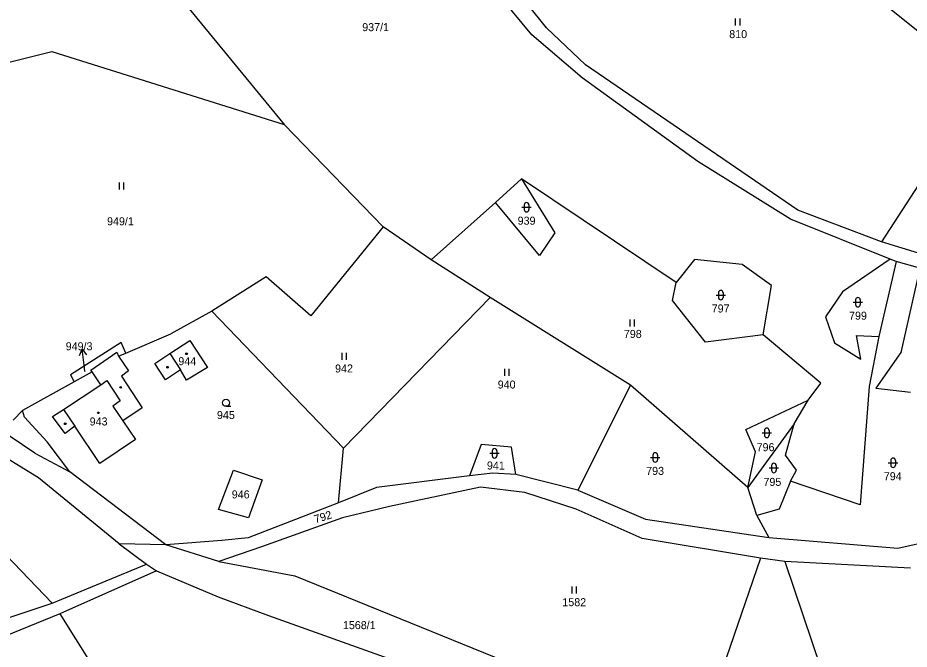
# Model space of a CAD drawing. Extents: x -670359 to -668019, y -978807 to -976674.
# Drawn here: x -669348.5 to -669159.3, y -977924.2 to -977790.2 of the extents above; entities that cross this region are included whole.
import ezdxf

# ---------------------------------------------------------------- set-up
doc = ezdxf.new("R2010")
doc.units = 0
for name, color, linetype in [('Hranice parcel', 7, 'Continuous'), ('Parcelní čísla', 7, 'Continuous'), ('Vnitřní kresba', 7, 'Continuous'), ('Značky budov', 7, 'Continuous'), ('Značky kultur', 7, 'Continuous')]:
    doc.layers.add(name, color=color, linetype=linetype)

msp = doc.modelspace()

# ---------------------------------------------------------------- linework, layer by layer
at = {"layer": 'Hranice parcel'}
for p, q in [((-669325.57, -977861.32), (-669316, -977857.26)), ((-669326.53, -977859.06), (-669337.33, -977865.97)), ((-669325.57, -977861.32), (-669326.53, -977859.06)), ((-669332.99, -977864.96), (-669327.49, -977861.17)), ((-669327.49, -977861.17), (-669327.09, -977861.96)), ((-669327.09, -977861.96), (-669325.57, -977861.32)), ((-669332.73, -977865.34), (-669336.54, -977867.45)), ((-669332.73, -977865.34), (-669332.99, -977864.96)), ((-669337.33, -977865.97), (-669336.54, -977867.45)), ((-669336.54, -977867.45), (-669347.5, -977873.51))]:
    msp.add_line(p, q, dxfattribs=at)
for points in [[(-669239.37, -977793.76), (-669277.73, -977747.47)], [(-669155.29, -977794.72), (-669193.7, -977763.96)], [(-669236.24, -977792.33), (-669255.54, -977768.2)], [(-669315.98, -977783.46), (-669291.93, -977812.85)], [(-669227.94, -977800.19), (-669236.24, -977792.33)], [(-669228.67, -977802.91), (-669239.37, -977793.76)], [(-669182.88, -977830.97), (-669227.94, -977800.19)], [(-669142.34, -977802.6), (-669165.12, -977837.74)], [(-669204.14, -977820.67), (-669228.67, -977802.91)], [(-669291.93, -977812.85), (-669270.94, -977834.54)], [(-669184.48, -977832.88), (-669204.14, -977820.67)], [(-669241.56, -977824.37), (-669247.06, -977829.36)], [(-669241.56, -977824.37), (-669234.47, -977835.84)], [(-669208.71, -977846.34), (-669241.56, -977824.37)], [(-669247.06, -977829.36), (-669260.75, -977841.51)], [(-669237.72, -977840.65), (-669247.06, -977829.36)], [(-669165.12, -977837.74), (-669182.88, -977830.97)], [(-669163.29, -977841.43), (-669184.48, -977832.88)], [(-669270.94, -977834.54), (-669286.27, -977853.41)], [(-669260.75, -977841.51), (-669270.94, -977834.54)], [(-669234.47, -977835.84), (-669237.72, -977840.65)], [(-669151.04, -977842.02), (-669165.12, -977837.74)], [(-669248.23, -977849.51), (-669260.75, -977841.51)], [(-669204.85, -977841.47), (-669208.71, -977846.34)], [(-669194.69, -977842.54), (-669204.85, -977841.47)], [(-669188.45, -977846.96), (-669194.69, -977842.54)], [(-669163.29, -977841.43), (-669173.4, -977848.36)], [(-669162.01, -977841.91), (-669165.67, -977857.83)], [(-669162.01, -977841.91), (-669163.29, -977841.43)], [(-669156.97, -977843.29), (-669162.01, -977841.91)], [(-669156.97, -977843.29), (-669161.03, -977861.2)], [(-669295.75, -977845.15), (-669307.31, -977852.42)], [(-669286.27, -977853.41), (-669295.75, -977845.15)], [(-669209.53, -977850.18), (-669208.71, -977846.34)], [(-669190.25, -977857.44), (-669188.45, -977846.96)], [(-669279.32, -977881.5), (-669248.23, -977849.51)], [(-669218.39, -977868.16), (-669248.23, -977849.51)], [(-669202.51, -977859), (-669209.53, -977850.18)], [(-669173.4, -977848.36), (-669177.03, -977853.63)], [(-669307.31, -977852.42), (-669316, -977857.26)], [(-669279.32, -977881.5), (-669307.31, -977852.42)], [(-669177.03, -977853.63), (-669175.12, -977859.16)], [(-669190.25, -977857.44), (-669202.51, -977859)], [(-669178.03, -977867.71), (-669190.25, -977857.44)], [(-669169.53, -977862.62), (-669170.47, -977857.57)], [(-669170.47, -977857.57), (-669165.67, -977857.83)], [(-669316.22, -977861.42), (-669311.99, -977858.68)], [(-669311.99, -977858.68), (-669308.2, -977864.41)], [(-669175.12, -977859.16), (-669169.53, -977862.62)], [(-669165.67, -977857.83), (-669167.78, -977868.46)], [(-669319.4, -977863.52), (-669316.22, -977861.42)], [(-669161.03, -977861.2), (-669166.34, -977868.79)], [(-669327.09, -977861.96), (-669324.99, -977865.07)], [(-669330.9, -977868.06), (-669332.73, -977865.34)], [(-669324.99, -977865.07), (-669326.51, -977866.27)], [(-669317.15, -977867.02), (-669319.4, -977863.52)], [(-669313.96, -977864.92), (-669317.15, -977867.02)], [(-669312.67, -977867.07), (-669313.96, -977864.92)], [(-669308.2, -977864.41), (-669312.67, -977867.07)], [(-669326.51, -977866.27), (-669322.07, -977872.96)], [(-669338.79, -977873.3), (-669330.9, -977868.06)], [(-669218.39, -977868.16), (-669229.6, -977890.45)], [(-669193.48, -977889.84), (-669218.39, -977868.16)], [(-669180.69, -977871.31), (-669178.03, -977867.71)], [(-669167.78, -977868.46), (-669169.63, -977893.58)], [(-669166.34, -977868.79), (-669158.98, -977869.61)], [(-669193.92, -977877.59), (-669180.69, -977871.31)], [(-669183.67, -977876.34), (-669180.69, -977871.31)], [(-669344.14, -977887.8), (-669365.81, -977874.5)], [(-669349.49, -977875.6), (-669347.5, -977873.51)], [(-669347.09, -977874.95), (-669347.5, -977873.51)], [(-669341.1, -977874.83), (-669338.79, -977873.3)], [(-669322.07, -977872.96), (-669326.22, -977875.7)], [(-669344.89, -977882.61), (-669355.46, -977875.53)], [(-669342.27, -977880.19), (-669347.09, -977874.95)], [(-669338.44, -977878.41), (-669341.1, -977874.83)], [(-669326.22, -977875.7), (-669323.48, -977879.68)], [(-669183.67, -977876.34), (-669193.48, -977889.84)], [(-669185.53, -977882.98), (-669183.67, -977876.34)], [(-669336.37, -977876.88), (-669338.44, -977878.41)], [(-669331.05, -977884.76), (-669336.37, -977876.88)], [(-669191.86, -977882.32), (-669193.92, -977877.59)], [(-669337.43, -977886.56), (-669342.27, -977880.19)], [(-669323.48, -977879.68), (-669331.05, -977884.76)], [(-669280.38, -977893.09), (-669279.32, -977881.5)], [(-669250.14, -977880.76), (-669252.58, -977887.41)], [(-669243.66, -977881.28), (-669250.14, -977880.76)], [(-669242.75, -977887.11), (-669243.66, -977881.28)], [(-669193.48, -977889.84), (-669191.86, -977882.32)], [(-669344.89, -977882.61), (-669337.43, -977886.56)], [(-669183.14, -977886.18), (-669185.53, -977882.98)], [(-669326.98, -977901.79), (-669344.14, -977887.8)], [(-669317.06, -977902.06), (-669337.43, -977886.56)], [(-669305.88, -977894.52), (-669302.73, -977886.19)], [(-669302.73, -977886.19), (-669296.64, -977888.23)], [(-669252.58, -977887.41), (-669272.35, -977889.85)], [(-669247.63, -977886.82), (-669252.58, -977887.41)], [(-669242.75, -977887.11), (-669247.63, -977886.82)], [(-669229.6, -977890.45), (-669242.75, -977887.11)], [(-669184.43, -977888.5), (-669183.14, -977886.18)], [(-669296.64, -977888.23), (-669299.55, -977896.32)], [(-669272.35, -977889.85), (-669280.38, -977893.09)], [(-669250.25, -977889.82), (-669269.58, -977893.93)], [(-669240.82, -977890.96), (-669250.25, -977889.82)], [(-669191.58, -977895.84), (-669193.48, -977889.84)], [(-669184.43, -977888.5), (-669186.85, -977894.5)], [(-669169.63, -977893.58), (-669184.43, -977888.5)], [(-669229.97, -977894.44), (-669240.82, -977890.96)], [(-669229.6, -977890.45), (-669215.21, -977896.58)], [(-669280.38, -977893.09), (-669299.61, -977900.56)], [(-669360.92, -977893.91), (-669341.2, -977914.44)], [(-669299.55, -977896.32), (-669305.88, -977894.52)], [(-669269.58, -977893.93), (-669279.54, -977896.31)], [(-669215.94, -977900.67), (-669229.97, -977894.44)], [(-669186.85, -977894.5), (-669191.58, -977895.84)], [(-669279.54, -977896.31), (-669296.73, -977902.44)], [(-669215.21, -977896.58), (-669189.03, -977900.49)], [(-669191.58, -977895.84), (-669189.03, -977900.49)], [(-669161.65, -977902.73), (-669146.51, -977899.33)], [(-669305.21, -977901.15), (-669317.06, -977902.06)], [(-669299.61, -977900.56), (-669305.21, -977901.15)], [(-669190.85, -977904.86), (-669215.94, -977900.67)], [(-669189.03, -977900.49), (-669161.65, -977902.73)], [(-669317.06, -977902.06), (-669326.98, -977901.79)], [(-669326.98, -977901.79), (-669321.18, -977906.17)], [(-669305.81, -977905.54), (-669317.06, -977902.06)], [(-669296.73, -977902.44), (-669305.81, -977905.54)], [(-669190.85, -977904.86), (-669205.42, -977947.35)], [(-669185.66, -977905.56), (-669190.85, -977904.86)], [(-669341.2, -977914.44), (-669321.18, -977906.17)], [(-669321.18, -977906.17), (-669319.04, -977907.56)], [(-669305.81, -977905.54), (-669289.69, -977908.65)], [(-669158.94, -977906.97), (-669185.66, -977905.56)], [(-669185.66, -977905.56), (-669166.49, -977962.39)], [(-669319.04, -977907.56), (-669339.55, -977916.69)], [(-669319.04, -977907.56), (-669305.97, -977913.06)], [(-669289.69, -977908.65), (-669245.12, -977926.75)], [(-669367.31, -977923.11), (-669341.2, -977914.44)], [(-669305.97, -977913.06), (-669295.28, -977917.01)], [(-669339.55, -977916.69), (-669353.13, -977922.23)], [(-669339.55, -977916.69), (-669326.24, -977937.87)], [(-669295.28, -977917.01), (-669268.73, -977926.5)]]:
    msp.add_lwpolyline(points, dxfattribs=at)
at = {"layer": 'Parcelní čísla'}
for p, q in [((-669335.42, -977861.87), (-669334.83, -977860.49)), ((-669334.26, -977865.28), (-669334.36, -977864.46))]:
    msp.add_line(p, q, dxfattribs=at)
msp.add_lwpolyline([(-669334.36, -977864.46), (-669334.83, -977860.49), (-669333.93, -977861.69)], dxfattribs=at)
at = {"layer": 'Vnitřní kresba'}
for points in [[(-669363.72, -977802.89), (-669341.3, -977797.34)], [(-669341.3, -977797.34), (-669291.93, -977812.85)], [(-669316.22, -977861.42), (-669313.96, -977864.92)], [(-669330.9, -977868.06), (-669329.62, -977867.17)], [(-669329.62, -977867.17), (-669326.8, -977871.47)], [(-669326.8, -977871.47), (-669328.31, -977872.6)], [(-669328.31, -977872.6), (-669326.22, -977875.7)], [(-669338.79, -977873.3), (-669336.37, -977876.88)]]:
    msp.add_lwpolyline(points, dxfattribs=at)
at = {"layer": 'Značky budov'}
for centre in [(-669312.68, -977861.49), (-669331.39, -977874.02)]:
    msp.add_circle(centre, 0.175, dxfattribs=at)
at = {"layer": 'Značky kultur'}
for p, q in [((-669196.17, -977790.29), (-669196.17, -977791.79)), ((-669195.17, -977791.79), (-669195.17, -977790.29)), ((-669326.98, -977825.13), (-669326.98, -977826.63)), ((-669325.98, -977826.63), (-669325.98, -977825.13)), ((-669241.49, -977830.39), (-669239.49, -977830.39)), ((-669240.99, -977829.89), (-669240.99, -977830.89)), ((-669239.99, -977829.89), (-669239.99, -977830.89)), ((-669200.25, -977849.02), (-669198.25, -977849.02)), ((-669199.75, -977848.52), (-669199.75, -977849.52)), ((-669198.75, -977848.52), (-669198.75, -977849.52)), ((-669170.63, -977850.05), (-669170.63, -977851.05)), ((-669169.63, -977850.05), (-669169.63, -977851.05)), ((-669171.13, -977850.55), (-669169.13, -977850.55)), ((-669218.54, -977854.22), (-669218.54, -977855.72)), ((-669217.54, -977855.72), (-669217.54, -977854.22)), ((-669279.71, -977861.25), (-669279.71, -977862.75)), ((-669278.71, -977862.75), (-669278.71, -977861.25)), ((-669245.18, -977864.66), (-669245.18, -977866.16)), ((-669244.18, -977866.16), (-669244.18, -977864.66)), ((-669304.29, -977872.63), (-669303.29, -977872.63)), ((-669190.48, -977878.26), (-669188.48, -977878.26)), ((-669189.98, -977877.76), (-669189.98, -977878.76)), ((-669188.98, -977877.76), (-669188.98, -977878.76)), ((-669247.79, -977882.11), (-669247.79, -977883.11)), ((-669246.79, -977882.11), (-669246.79, -977883.11)), ((-669248.29, -977882.61), (-669246.29, -977882.61)), ((-669214.16, -977883.49), (-669212.16, -977883.49)), ((-669213.66, -977882.99), (-669213.66, -977883.99)), ((-669212.66, -977882.99), (-669212.66, -977883.99)), ((-669163.18, -977884.12), (-669163.18, -977885.12)), ((-669162.18, -977884.12), (-669162.18, -977885.12)), ((-669188.97, -977885.72), (-669186.97, -977885.72)), ((-669188.47, -977885.22), (-669188.47, -977886.22)), ((-669187.47, -977885.22), (-669187.47, -977886.22)), ((-669163.68, -977884.62), (-669161.68, -977884.62)), ((-669230.89, -977910.86), (-669230.89, -977912.36)), ((-669229.89, -977912.36), (-669229.89, -977910.86))]:
    msp.add_line(p, q, dxfattribs=at)
for centre, radius in [((-669312.68, -977861.49), 0.175), ((-669316.71, -977864.33), 0.175), ((-669326.66, -977868.62), 0.175), ((-669304.29, -977871.88), 0.75), ((-669331.39, -977874.02), 0.175), ((-669338.44, -977876.34), 0.175)]:
    msp.add_circle(centre, radius, dxfattribs=at)
for centre, start, end in [((-669240.49, -977829.89), 0, 180), ((-669240.49, -977830.89), 180, 0), ((-669199.25, -977848.52), 0, 180), ((-669199.25, -977849.52), 180, 0), ((-669170.13, -977850.05), 0, 180), ((-669170.13, -977851.05), 180, 0), ((-669189.48, -977877.76), 0, 180), ((-669189.48, -977878.76), 180, 0), ((-669247.29, -977882.11), 0, 180), ((-669247.29, -977883.11), 180, 0), ((-669213.16, -977882.99), 0, 180), ((-669213.16, -977883.99), 180, 0), ((-669162.68, -977884.12), 0, 180), ((-669187.97, -977885.22), 0, 180), ((-669162.68, -977885.12), 180, 0), ((-669187.97, -977886.22), 180, 0)]:
    msp.add_arc(centre, 0.5, start, end, dxfattribs=at)

# ---------------------------------------------------------------- texts
at = {"layer": 'Parcelní čísla'}
for s, height, p in [('937/1', 1.7, (-669275.38, -977793.01)), ('810', 1.7, (-669197.46, -977794.49)), ('949/1', 1.7, (-669329.55, -977834.21)), ('939', 1.7, (-669242.38, -977834.09)), ('797', 1.7, (-669201.18, -977852.72)), ('799', 1.7, (-669172.02, -977854.25)), ('798', 1.7, (-669219.83, -977858.12)), ('949/3', 1.7, (-669338.33, -977860.74)), ('944', 1.7, (-669314.42, -977863.91)), ('949/3', 0.1, (-669334.46, -977865.28)), ('942', 1.7, (-669281.14, -977865.45)), ('940', 1.7, (-669246.61, -977868.86)), ('945', 1.7, (-669306.22, -977875.33)), ('943', 1.7, (-669333.24, -977876.7)), ('796', 1.7, (-669191.64, -977882.16)), ('941', 1.7, (-669248.9, -977886.05)), ('793', 1.7, (-669215.09, -977887.19)), ('795', 1.7, (-669190.19, -977889.52)), ('794', 1.7, (-669164.64, -977888.32)), ('946', 1.7, (-669303.07, -977892.18)), ('1582', 1.7, (-669232.89, -977915.06)), ('1568/1', 1.7, (-669279.48, -977919.93))]:
    msp.add_text(s, height=height, dxfattribs=at).set_placement(p)
msp.add_text('792', height=1.7, rotation=16.8763, dxfattribs=at).set_placement((-669285.29, -977897.47))

doc.saveas('drawing.dxf')
